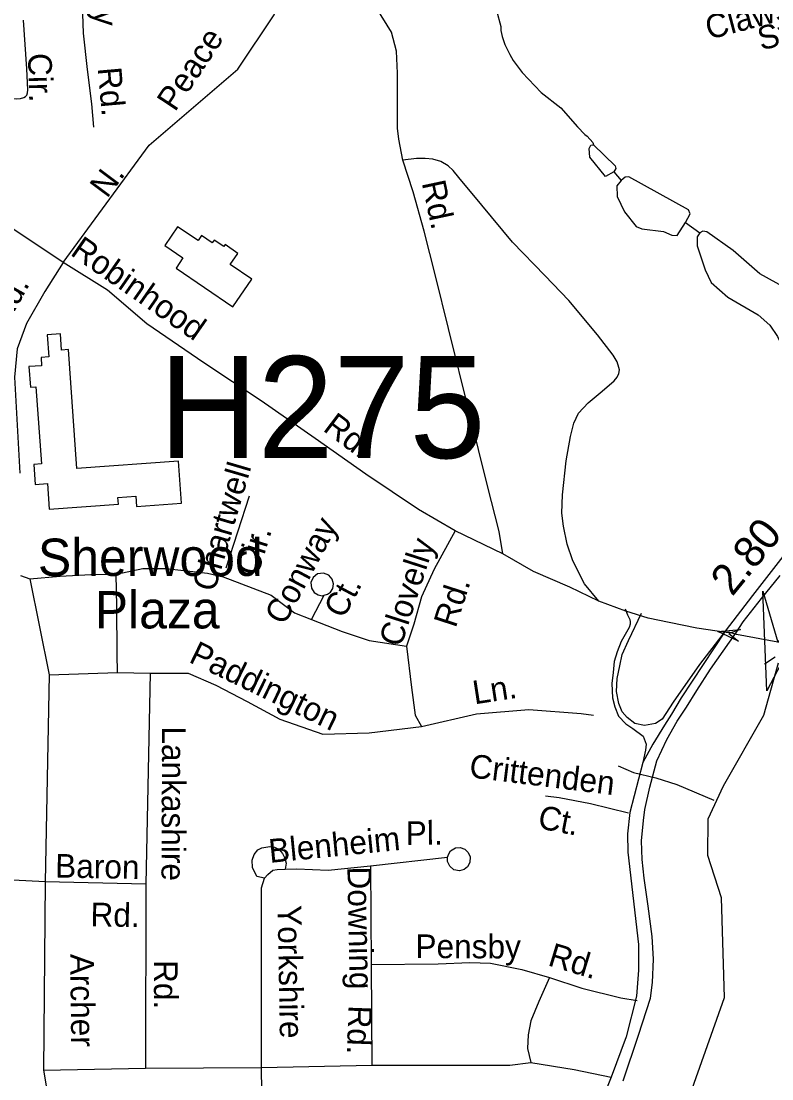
# Model space of a CAD drawing. Extents: x 1547597 to 1699558, y 810033 to 920809.
# Drawn here: x 1611614 to 1614630, y 860710 to 864963 of the extents above; entities that cross this region are included whole.
import ezdxf

# ---------------------------------------------------------------- set-up
doc = ezdxf.new("R2010")
doc.units = 0
for name, color, linetype in [('Exist Cultural Shopping Center Building Footprint', 7, 'Continuous'), ('Exist Cultural Shopping Center Building Label', 7, 'Continuous'), ('Exist Cultural Warehouse Building Footprint', 7, 'Continuous'), ('Exist Hydrographic Creek Single Shore', 7, 'Continuous'), ('Exist Hydrographic Misc Water Feature', 7, 'Continuous'), ('Exist Road Non-System Type 51', 7, 'Continuous'), ('Exist Road Non-System Type 51 Label', 7, 'Continuous'), ('Exist Road Primary Interstate Ramp 1 Lane Attributed', 7, 'Continuous'), ('Exist Road Primary NC Divided Attributed', 7, 'Continuous'), ('Exist Road Primary NC Service Mileage Hundredths English Label', 7, 'Continuous'), ('Exist Road Primary NC UnDivided 4 Lane Attributed', 7, 'Continuous'), ('Exist Road Primary US Structure Non-Sys NCDOT Number Label', 7, 'Continuous'), ('Exist Road Secondary Structure Culvert Attributed CELL', 7, 'Continuous'), ('Exist Road Secondary Structure Culvert CELL', 7, 'Continuous'), ('Exist Road Secondary Structure Standard Bridge Attributed CELL', 7, 'Continuous'), ('Exist Road Secondary Type 51 Undivided 4 Lane Attributed', 7, 'Continuous')]:
    doc.layers.add(name, color=color, linetype=linetype)

msp = doc.modelspace()

# ---------------------------------------------------------------- linework, layer by layer
at = {"layer": 'Exist Cultural Shopping Center Building Footprint'}
msp.add_lwpolyline([(1611838.2, 863164.9), (1611804.5, 863642.4), (1611776.7, 863640.4), (1611772.1, 863705.6), (1611718.6, 863701.9), (1611724.9, 863612.9), (1611694, 863610.7), (1611696.3, 863578), (1611645.5, 863574.4), (1611651.4, 863491.1), (1611673.8, 863492.7), (1611695.7, 863182.6), (1611664.7, 863180.4), (1611670.4, 863100.3), (1611719.5, 863103.7), (1611726.7, 863001.2), (1612005.2, 863020.9), (1612003.3, 863048.1), (1612074.5, 863053.1), (1612077.4, 863011.7), (1612258.8, 863024.6), (1612246.8, 863193.7)], close=True, dxfattribs=at)
at = {"layer": 'Exist Cultural Warehouse Building Footprint'}
msp.add_lwpolyline([(1612236.4, 863970.2), (1612464.9, 863814.7), (1612540.6, 863926), (1612454.2, 863984.8), (1612484.7, 864029.6), (1612433.3, 864064.6), (1612428, 864056.9), (1612389.3, 864083.3), (1612381.5, 864071.8), (1612338.5, 864101.1), (1612324.9, 864081.1), (1612242.9, 864136.8), (1612191.1, 864060.7), (1612264.2, 864011)], close=True, dxfattribs=at)
at = {"layer": 'Exist Hydrographic Creek Single Shore'}
msp.add_lwpolyline([(1613652.6, 858889.6), (1613841.5, 859271.2), (1614203.9, 860371.1), (1614439.9, 861036.9), (1614428.1, 861438.6), (1614372.7, 861607.8), (1614374.7, 861755.6), (1614435.7, 861889), (1614597.7, 862172.7), (1614656.9, 862383.5)], dxfattribs=at)
at = {"layer": 'Exist Hydrographic Misc Water Feature'}
for p, q in [((1613995.9, 864357.8), (1614025.5, 864322.3)), ((1614283, 864153.7), (1614341.4, 864112.2))]:
    msp.add_line(p, q, dxfattribs=at)
for points in [[(1613545.1, 865136.2), (1613541.8, 865134.1), (1613533.5, 865110.2), (1613525.1, 865078.3), (1613524.1, 865006.4), (1613541.2, 864942.2), (1613541, 864926.2), (1613546.6, 864902.1), (1613558.2, 864869.9), (1613577.6, 864829.7), (1613591.3, 864805.5), (1613626.6, 864757), (1613703.5, 864675.9), (1613782.6, 864614.8), (1613849.5, 864537.9), (1613879, 864507.6), (1613889, 864501.4), (1613910.6, 864475.1), (1613913.9, 864466.6)], [(1613995.9, 864357.8), (1613961.5, 864339.3), (1613899.3, 864416.3), (1613896.3, 864450.6), (1613903.7, 864465.1), (1613913.9, 864466.6)], [(1613913.9, 864466.6), (1614000.4, 864380.9), (1614002.9, 864371), (1613995.9, 864357.8)], [(1614025.5, 864322.3), (1614007.7, 864300.7), (1614008.5, 864258.6), (1614038.7, 864196.6), (1614085.6, 864137.4), (1614108.6, 864128.1), (1614195.4, 864117.3), (1614229.1, 864102.7), (1614249.7, 864101.3), (1614283, 864153.7)], [(1614283, 864153.7), (1614302.4, 864188), (1614295.7, 864205.2), (1614056.1, 864337.8), (1614041.5, 864335.4), (1614025.5, 864322.3)], [(1614341.4, 864112.2), (1614330.6, 864096.5), (1614330.6, 864059.6), (1614362, 863963.7), (1614386.5, 863912.4), (1614453.6, 863853.4), (1614575.5, 863783), (1614622.5, 863740.5), (1614652.5, 863695.6), (1614687, 863627.5), (1614721.3, 863521.7), (1614756.3, 863437.7), (1614766.1, 863427.4), (1614790.4, 863425.8), (1614872.5, 863472.9)], [(1614872.5, 863472.9), (1614934.6, 863515.4), (1614936.6, 863532.6), (1614915.6, 863611.2), (1614878, 863720.9), (1614845.9, 863777.4), (1614819.2, 863804.7), (1614740.6, 863860.8), (1614582.1, 863947.9), (1614474.9, 864041.3), (1614368.9, 864116.1), (1614352.6, 864118.9), (1614341.4, 864112.2)], [(1614012.5, 861969.5), (1614074.7, 861942.1), (1614164.6, 861921.3), (1614248.5, 861894.5), (1614396.8, 861830.2)]]:
    msp.add_lwpolyline(points, dxfattribs=at)
at = {"layer": 'Exist Road Non-System Type 51'}
msp.add_line((1612780.4, 862557.5), (1612832.2, 862654.5), dxfattribs=at)
for points in [[(1611906.1, 864536.8), (1611897.8, 864631), (1611880.4, 864769.2), (1611865.1, 864915.4), (1611862.5, 864993.3), (1611862, 865079.4), (1611859.5, 865261.3), (1611858.5, 865419.2), (1611856.4, 865521.3), (1611860.1, 865613.1)], [(1611782.8, 863992.3), (1612127.9, 864465), (1612484.3, 864770.3), (1612630.9, 864988.3), (1612781.4, 865313.3)], [(1613148.2, 864404.1), (1613131.9, 864488.3), (1613126.4, 864533), (1613126, 864600.5), (1613126.9, 864754.3), (1613122.5, 864842.3), (1613101.8, 864918.7), (1613043.7, 865013.8), (1612952.6, 865157.3), (1612886.3, 865252.5), (1612860.6, 865277.7), (1612828.9, 865301.4), (1612781.4, 865313.3)], [(1611384.9, 864984.2), (1611430.1, 864945.3), (1611437.9, 864933.3), (1611440.8, 864879.2), (1611436.5, 864757.2), (1611435.5, 864699.4), (1611438.6, 864682.9), (1611441.6, 864675.3), (1611447.1, 864668.8), (1611452.4, 864664.2), (1611459.7, 864661.3), (1611500.7, 864656.3), (1611596.4, 864650.5), (1611612.2, 864652), (1611624.5, 864655.9), (1611631.2, 864659.8), (1611636.7, 864665.7), (1611640.1, 864674.8), (1611641, 864687.6), (1611636.7, 864771.6), (1611624.3, 864967.7)], [(1613935.7, 862631.7), (1613877.7, 862701), (1613831.2, 862793.8), (1613808.3, 862860.1), (1613793.5, 862932.2), (1613786.4, 862984.4), (1613789.7, 863058.3), (1613803.9, 863195.9), (1613821.5, 863293.6), (1613834.4, 863347.4), (1613853, 863387), (1613891.7, 863428.5), (1613948.2, 863475.4), (1613996.9, 863516.6), (1614009.4, 863531.6), (1614015.5, 863546.2), (1614017.6, 863560.6), (1614015.8, 863570.2), (1614009.3, 863593.8), (1613992.6, 863620.5), (1613930, 863701.7), (1613814.5, 863839.5), (1613718.4, 863940.9), (1613588.6, 864075), (1613465.1, 864222.8), (1613373.1, 864334.3), (1613350.1, 864363), (1613330.1, 864381), (1613299.8, 864399.2), (1613268.6, 864407.9), (1613237.2, 864411.7), (1613202.6, 864411), (1613148.2, 864404.1)], [(1613549.7, 862820.7), (1613534.2, 862911.6), (1613487.7, 863094.5), (1613415.2, 863387.5), (1613331.6, 863727), (1613279.5, 863939.8), (1613232.9, 864118.6), (1613189.9, 864277.4), (1613148.2, 864404.1)], [(1611782.8, 863992.3), (1611709.5, 863875.9), (1611636.2, 863746.9), (1611598.2, 863645.7), (1611588.1, 863531.8), (1611608.5, 863145.5)], [(1614446.6, 862505.6), (1614329.1, 862523.1), (1614217.2, 862544.7), (1614133.5, 862563.2), (1614044.2, 862590.9), (1613935.7, 862631.7), (1613819, 862687.9), (1613672.2, 862750.6), (1613549.7, 862820.7), (1613357.7, 862914.2), (1613210.2, 862999.2), (1612999.3, 863141.9), (1612795.7, 863285.3), (1612578.7, 863437.2), (1612348.4, 863590), (1612119.4, 863746.1), (1611960.8, 863881.2), (1611782.8, 863992.3)], [(1612530.2, 863052.8), (1612436.6, 862764.4)], [(1613357.7, 862914.2), (1613273.5, 862759.3), (1613222.9, 862648), (1613192.6, 862539.2), (1613162.2, 862450.6)], [(1611649, 862720.9), (1611770.6, 862732.1), (1611894.6, 862737.8), (1611996.5, 862739.9)], [(1611996.5, 862739.9), (1612102.9, 862761.8), (1612196.4, 862761.8), (1612267.2, 862754.3), (1612363.3, 862744.1), (1612426.5, 862729)], [(1612001.8, 862344.4), (1612000.6, 862418.1), (1611998, 862610), (1611996.5, 862739.9)], [(1612832.2, 862654.5), (1612845.3, 862658.7), (1612856.7, 862667.4), (1612866.4, 862681.9), (1612869.4, 862701), (1612863.5, 862719.5), (1612850.2, 862735.4), (1612828.6, 862743.7), (1612805.3, 862740.5), (1612787.6, 862726.3), (1612778.6, 862705.7), (1612780.8, 862683.4), (1612791.6, 862666.2), (1612808, 862656), (1612823.4, 862652.7), (1612832.2, 862654.5)], [(1611611.1, 862733.6), (1611649, 862720.9)], [(1611649, 862720.9), (1611726.2, 862334.2)], [(1612426.5, 862729), (1612618.7, 862655.6), (1612712.2, 862584.7), (1612780.4, 862557.5)], [(1612780.4, 862557.5), (1612904.4, 862508.8), (1613013.1, 862473.4), (1613162.2, 862450.6)], [(1614488, 862496.6), (1614461.5, 862504.4), (1614446.6, 862505.6)], [(1615270.2, 862348.2), (1615009.1, 862396.7), (1614801.2, 862445), (1614654.1, 862466.2), (1614488, 862496.6)], [(1613162.2, 862450.6), (1613182.5, 862283.6), (1613197.6, 862172.3), (1613222.9, 862126.7)], [(1611726.2, 862334.2), (1611711.2, 861502.8)], [(1611726.2, 862334.2), (1612001.8, 862344.4)], [(1612001.8, 862344.4), (1612133.2, 862341.8)], [(1612133.2, 862341.8), (1612115.7, 861492.6)], [(1612133.2, 862341.8), (1612284.9, 862341.8), (1612396.2, 862293.7), (1612522.6, 862228), (1612654.1, 862157.1), (1612826, 862096.4), (1613013.1, 862101.4), (1613222.9, 862126.7)], [(1613222.9, 862126.7), (1613444.1, 862177.4), (1613653.9, 862195.2), (1613863.8, 862180), (1613914.4, 862172.4)], [(1613720.3, 861848.7), (1613776.2, 861841.7), (1613901.6, 861817.4), (1614053.9, 861779.3)], [(1612592.4, 861517.1), (1612560.5, 861523.7), (1612543.2, 861560.1), (1612541.8, 861590.1), (1612550.3, 861612), (1612564.5, 861631.7), (1612580.6, 861639.4), (1612612.8, 861644.7), (1612632.7, 861642.3), (1612650.5, 861631.9), (1612664.2, 861615.9), (1612673.8, 861597.6), (1612679.4, 861577.5), (1612675, 861553.6)], [(1613327.3, 861602), (1613332, 861615.6), (1613339.8, 861627.4), (1613359.5, 861638.8), (1613378.7, 861640), (1613397, 861633.6), (1613410.7, 861621), (1613418.4, 861603), (1613417.5, 861580.8), (1613407.1, 861562.8), (1613393.9, 861552.7), (1613375.4, 861547.2), (1613353.1, 861550.9), (1613336.1, 861564.8), (1613326.9, 861583.8), (1613327.3, 861602)], [(1613017.7, 861567.4), (1613327.3, 861602)], [(1612580.3, 860755.2), (1612580.3, 861478.9), (1612592.4, 861517.1), (1612605.6, 861532), (1612625.8, 861549.7), (1612643.5, 861552.2), (1612675, 861553.6), (1612721.9, 861554.8), (1612848.3, 861549.7), (1613017.7, 861567.4)], [(1613017.7, 861567.4), (1613020.2, 861170.2)], [(1611711.2, 861502.8), (1611580.7, 861509.5), (1611504.8, 861493.9), (1611474.3, 861483)], [(1611711.2, 861502.8), (1611703.6, 860745.8)], [(1612115.7, 861492.6), (1611711.2, 861502.8)], [(1612115.7, 861492.6), (1612113.2, 860753.3)], [(1613020.2, 861170.2), (1613289.9, 861173.2), (1613416.3, 861178.2), (1613499.7, 861175.7), (1613626.1, 861150.4), (1613737.4, 861117.5)], [(1613020.2, 861170.2), (1613022.8, 860765.3)], [(1613737.4, 861117.5), (1613694.4, 861021.3), (1613661.5, 860942.9), (1613651.4, 860887.2), (1613648.9, 860831.6), (1613661.5, 860775.9)], [(1613737.4, 861117.5), (1613866.3, 861074.5), (1614023.1, 861036.5), (1614089.4, 861025.1)], [(1611703.6, 860745.8), (1612113.2, 860753.3)], [(1611703.6, 860745.8), (1611741.9, 860524.3), (1611848.1, 860286.5), (1611885, 860225.7)], [(1612113.2, 860753.3), (1612580.3, 860755.2)], [(1612577.8, 860329.5), (1612583.4, 860405.2), (1612582.8, 860559.7), (1612580.3, 860755.2)], [(1612580.3, 860755.2), (1613022.8, 860765.3)], [(1613022.8, 860765.3), (1613353.1, 860765.8), (1613578.1, 860765.8), (1613661.5, 860775.9)], [(1613661.5, 860775.9), (1613836, 860748.1), (1613984.5, 860717.4)]]:
    msp.add_lwpolyline(points, dxfattribs=at)
at = {"layer": 'Exist Road Primary Interstate Ramp 1 Lane Attributed'}
for points in [[(1614041, 862600.3), (1614050.1, 862575.8), (1614057, 862562.4), (1614059.8, 862556.8), (1614060.8, 862548.3), (1614061.3, 862538.4), (1614056.7, 862525), (1614025.5, 862469), (1614008.9, 862427.3), (1613997.1, 862387.8), (1613992.2, 862343.7), (1613987.3, 862300.5), (1613990.3, 862242.6), (1613999.1, 862206.3), (1614014.8, 862168), (1614044.2, 862137.6), (1614072.1, 862118.8), (1614113.8, 862087.6), (1614125.5, 862056.2), (1614122.6, 862031.7), (1614112, 861982)], [(1614443.1, 862510.8), (1614339.6, 862376.9), (1614234, 862224.5), (1614189.3, 862156.3), (1614162.8, 862139.6), (1614118.7, 862130.8), (1614079.5, 862138.6), (1614049.1, 862163.1), (1614029.5, 862186.7), (1614015.7, 862220), (1614006.8, 862267.4), (1614008.9, 862319.4), (1614019.7, 862371.1), (1614029.6, 862417), (1614054.6, 862473.1), (1614106.7, 862582.5)]]:
    msp.add_lwpolyline(points, dxfattribs=at)
at = {"layer": 'Exist Road Primary NC Divided Attributed'}
for points in [[(1614033.5, 860701.7), (1614094.3, 860886.4), (1614142.6, 861034.7), (1614151.1, 861097.8), (1614155.4, 861191.3), (1614149, 861282.8), (1614134.1, 861404.6), (1614117.1, 861516.6), (1614109.3, 861591.7), (1614107.2, 861667.5), (1614114.3, 861749.7), (1614120.7, 861793), (1614139.8, 861883.7), (1614168.7, 861988.8), (1614207.8, 862075), (1614250.3, 862148.7), (1614287.9, 862205.4), (1614329, 862271.3), (1614383.6, 862357), (1614485.6, 862503)], [(1614112, 861982), (1614060.4, 861780.9), (1614050.5, 861695.2), (1614051.2, 861621.5), (1614094.4, 861250.9), (1614094.3, 861147.3), (1614086.7, 861043.2), (1614045.5, 860878.6), (1613984.5, 860717.4), (1613906.7, 860524.5)]]:
    msp.add_lwpolyline(points, dxfattribs=at)
at = {"layer": 'Exist Road Primary NC UnDivided 4 Lane Attributed'}
for points in [[(1617220.5, 865050.1), (1617141.6, 864928.7), (1617096.1, 864864.9), (1617043.8, 864804.7), (1616914.4, 864664.3), (1616784, 864558.1), (1616595.9, 864441.1), (1616379.8, 864314.3), (1616183.5, 864196.6), (1616051.7, 864118.7), (1615949.6, 864052.8), (1615836.7, 863977.3), (1615718.4, 863890.6), (1615569.8, 863764.4), (1615412.5, 863624.1), (1615231.1, 863435.6), (1615142.5, 863336.4), (1615050.8, 863231.2), (1614941.3, 863113.1), (1614804.5, 862962.2), (1614693.2, 862835.4), (1614553.1, 862653.9), (1614443.1, 862510.8)], [(1614485.6, 862503), (1614514.7, 862547.7), (1614589.1, 862641.2), (1614663.5, 862734.7)], [(1614443.1, 862510.8), (1614266.6, 862242.2), (1614227, 862176.2), (1614198.5, 862132.4), (1614152.4, 862056.6), (1614112, 861982)]]:
    msp.add_lwpolyline(points, dxfattribs=at)
at = {"layer": 'Exist Road Secondary Structure Culvert Attributed CELL'}
msp.add_lwpolyline([(1614796.1, 862625.1), (1614610, 862271.1), (1614594.2, 862670.8), (1614654.1, 862466.2)], close=True, dxfattribs=at)
at = {"layer": 'Exist Road Secondary Structure Culvert CELL'}
msp.add_line((1614600.8, 862378.9), (1614643.3, 862406.7), dxfattribs=at)
at = {"layer": 'Exist Road Secondary Structure Standard Bridge Attributed CELL'}
msp.add_lwpolyline([(1614496, 862470.8), (1614413.2, 862509.6), (1614504.3, 862517.4), (1614458.2, 862501.5)], close=True, dxfattribs=at)
at = {"layer": 'Exist Road Secondary Type 51 Undivided 4 Lane Attributed'}
msp.add_lwpolyline([(1611782.8, 863992.3), (1611322.1, 864299.7), (1611179.7, 864389.5), (1611037.1, 864480.8), (1610841.1, 864603.1), (1610699, 864703.7), (1610563.9, 864780.4), (1610427.9, 864875.2), (1610268, 864976.5)], dxfattribs=at)

# ---------------------------------------------------------------- texts
at = {"layer": 'Exist Cultural Shopping Center Building Label'}
for s, p in [('Sherwood', (1611681.6, 862732.6)), ('Plaza', (1611910, 862521.5))]:
    msp.add_text(s, height=150, dxfattribs=at).set_placement(p)
at = {"layer": 'Exist Road Non-System Type 51 Label'}
for s, rotation, p in [('Greenvalley', 270.7903, (1611898, 865622)), ('Clawson', 14.763, (1614377.6, 864888.4)), ('St.', 14.763, (1614587.6, 864844.7)), ('Peace', 56.4048, (1612232.7, 864595.5)), ('Cir.', 271.5712, (1611641.5, 864833.7)), ('Rd.', 275.0307, (1611921.6, 864774.7)), ('N.', 53.2546, (1611959.3, 864247.7)), ('Rd.', 282.0913, (1613223.5, 864313.2)), ('Robinhood', 325.1315, (1611807.8, 864025.8)), ('Rd.', 60.5593, (1611553.9, 863735.2)), ('Rd.', 322.945, (1612822.9, 863319.2)), ('Chartwell', 73.6478, (1612391, 862664.3)), ('Conway', 61.9005, (1612671.8, 862530.4)), ('Cir.', 72.6474, (1612563.6, 862727.4)), ('Clovelly', 72.103, (1613140.2, 862442.1)), ('Ct.', 61.9005, (1612909.6, 862556.7)), ('Rd.', 72.103, (1613359.9, 862520.2)), ('Paddington', 334.1515, (1612283.7, 862388.1)), ('Ln.', 8.792, (1613435.9, 862215.9)), ('Lankashire', 269.7547, (1612180.5, 862127.5)), ('Crittenden', 352.9259, (1613411.3, 861923.2)), ('Ct.', 349.0059, (1613686, 861718.8)), ('Blenheim', 5.658, (1612613.5, 861578.6)), ('Pl.', 0.8125, (1613160.1, 861650.3)), ('Baron', 358.9729, (1611750.1, 861520.1)), ('Downing', 271.1001, (1612924.8, 861563.4)), ('Rd.', 358.9729, (1611892.1, 861324.1)), ('Yorkshire', 270.9876, (1612644.6, 861408.1)), ('Pensby', 359.7648, (1613198.1, 861196)), ('Rd.', 343.1421, (1613726.5, 861167.6)), ('Archer', 270.6425, (1611811.2, 861212.7)), ('Rd.', 270.0202, (1612147.9, 861187.9)), ('Rd.', 267.8134, (1612930, 861006.9))]:
    msp.add_text(s, height=95, rotation=rotation, dxfattribs=at).set_placement(p)
at = {"layer": 'Exist Road Primary NC Service Mileage Hundredths English Label'}
msp.add_text('2.80', height=125, rotation=50.7845, dxfattribs=at).set_placement((1614471.2, 862646.7))
at = {"layer": 'Exist Road Primary US Structure Non-Sys NCDOT Number Label'}
msp.add_text('H275', height=410.1, dxfattribs=at).set_placement((1612168.6, 863206.3))

doc.saveas('drawing.dxf')
